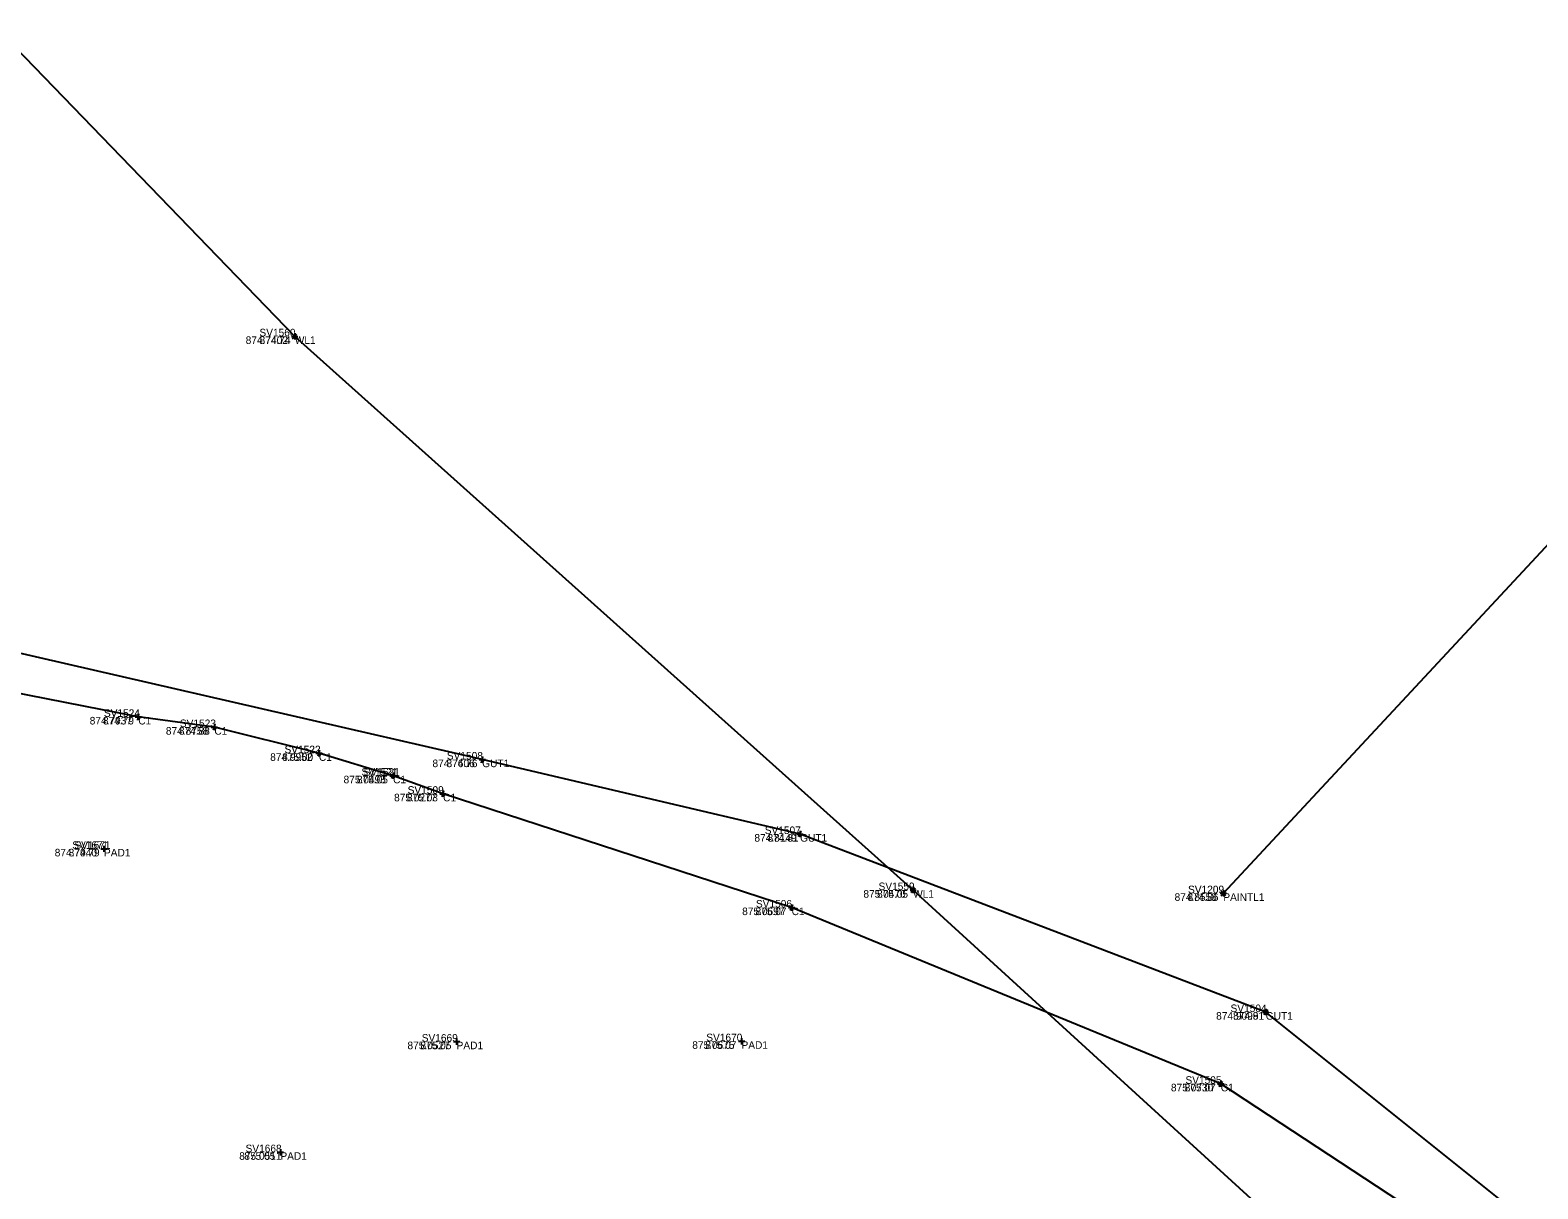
# Model space of a CAD drawing. Extents: x 1475924 to 1484301, y 375879 to 383357.
# Drawn here: x 1480175.83 to 1480187.77, y 379382.77 to 379391.95 of the extents above; entities that cross this region are included whole.
import ezdxf

# ---------------------------------------------------------------- set-up
doc = ezdxf.new("R2010")
doc.units = 0
for name, color, linetype in [('PM_X_Crosswalk', 7, 'Continuous'), ('PV_X_Curb', 7, 'Continuous'), ('SV_X_Shot_Marker', 7, 'Continuous'), ('SV_X_Text_Comment', 7, 'Continuous'), ('SV_X_Text_Elevation', 7, 'Continuous'), ('SV_X_Text_Name', 7, 'Continuous'), ('UT_X_Water', 7, 'Continuous')]:
    doc.layers.add(name, color=color, linetype=linetype)

# ---------------------------------------------------------------- blocks, each defined once
blk = doc.blocks.new('GTM')
at = {"layer": 'SV_X_Shot_Marker'}
for p, q in [((-0.075, 0), (0.075, 0)), ((0, 0.075), (0, -0.075)), ((0, 0), (0, 0))]:
    blk.add_line(p, q, dxfattribs=at)

msp = doc.modelspace()

# ---------------------------------------------------------------- linework, layer by layer
at = {"layer": 'PM_X_Crosswalk'}
msp.add_line((1480185.279, 379385.114), (1480212.329, 379414.193), dxfattribs=at)
at = {"layer": 'PV_X_Curb'}
for points in [[(1480233.83, 379339.39), (1480215.875, 379356.288), (1480200.731, 379370.664), (1480190.903, 379379.712), (1480187.53, 379382.642), (1480185.615, 379384.173), (1480181.928, 379385.583), (1480179.411, 379386.173), (1480174.793, 379387.235), (1480172.715, 379387.432), (1480170.332, 379387.359), (1480168.876, 379387.382), (1480166.808, 379386.944), (1480164.881, 379386.368), (1480162.883, 379385.531), (1480159.898, 379383.853), (1480158.052, 379382.754), (1480156.183, 379381.403), (1480155.05, 379380.342)], [(1480233.297, 379339.4), (1480215.447, 379356.074), (1480200.436, 379370.31), (1480191.889, 379378.223), (1480190.185, 379379.842), (1480188.303, 379381.604), (1480185.259, 379383.605), (1480181.861, 379385.001), (1480179.101, 379385.902), (1480178.705, 379386.045), (1480178.118, 379386.223), (1480177.29, 379386.43), (1480176.688, 379386.511), (1480174.95, 379386.851), (1480173.419, 379387.005), (1480171.202, 379387.128), (1480169.933, 379386.966), (1480168.123, 379386.781), (1480166.87, 379386.446), (1480165.488, 379386.008), (1480163.201, 379385.04), (1480160.165, 379383.332), (1480157.23, 379381.331), (1480156.058, 379380.439)]]:
    msp.add_lwpolyline(points, dxfattribs=at)
at = {"layer": 'SV_X_Shot_Marker'}
for p, q in [((1480177.946, 379389.508), (1480177.908, 379389.541)), ((1480177.91, 379389.506), (1480177.944, 379389.543)), ((1480177.927, 379389.525), (1480177.927, 379389.525)), ((1480176.713, 379386.507), (1480176.663, 379386.514)), ((1480176.685, 379386.486), (1480176.691, 379386.535)), ((1480176.688, 379386.511), (1480176.688, 379386.511)), ((1480177.314, 379386.424), (1480177.266, 379386.436)), ((1480177.284, 379386.405), (1480177.296, 379386.454)), ((1480177.29, 379386.43), (1480177.29, 379386.43)), ((1480178.142, 379386.215), (1480178.094, 379386.23)), ((1480178.111, 379386.199), (1480178.126, 379386.247)), ((1480178.118, 379386.223), (1480178.118, 379386.223)), ((1480179.435, 379386.167), (1480179.387, 379386.179)), ((1480179.405, 379386.148), (1480179.417, 379386.197)), ((1480179.411, 379386.173), (1480179.411, 379386.173)), ((1480178.728, 379386.037), (1480178.681, 379386.054)), ((1480178.696, 379386.022), (1480178.713, 379386.069)), ((1480178.705, 379386.045), (1480178.705, 379386.045)), ((1480179.124, 379385.895), (1480179.077, 379385.91)), ((1480179.093, 379385.879), (1480179.108, 379385.926)), ((1480179.101, 379385.902), (1480179.101, 379385.902)), ((1480181.951, 379385.574), (1480181.905, 379385.592)), ((1480181.919, 379385.56), (1480181.937, 379385.607)), ((1480181.928, 379385.583), (1480181.928, 379385.583)), ((1480176.391, 379385.466), (1480176.441, 379385.466)), ((1480176.416, 379385.491), (1480176.416, 379385.441)), ((1480176.416, 379385.466), (1480176.416, 379385.466)), ((1480182.842, 379385.122), (1480182.805, 379385.156)), ((1480182.806, 379385.12), (1480182.84, 379385.157)), ((1480182.823, 379385.139), (1480182.823, 379385.139)), ((1480185.26, 379385.131), (1480185.297, 379385.097)), ((1480185.261, 379385.095), (1480185.296, 379385.132)), ((1480185.279, 379385.114), (1480185.279, 379385.114)), ((1480181.884, 379384.992), (1480181.838, 379385.011)), ((1480181.851, 379384.978), (1480181.871, 379385.024)), ((1480181.861, 379385.001), (1480181.861, 379385.001)), ((1480185.635, 379384.157), (1480185.595, 379384.189)), ((1480185.599, 379384.154), (1480185.631, 379384.193)), ((1480185.615, 379384.173), (1480185.615, 379384.173)), ((1480179.183, 379383.939), (1480179.233, 379383.939)), ((1480179.208, 379383.964), (1480179.208, 379383.914)), ((1480179.208, 379383.939), (1480179.208, 379383.939)), ((1480181.439, 379383.942), (1480181.489, 379383.942)), ((1480181.464, 379383.967), (1480181.464, 379383.917)), ((1480181.464, 379383.942), (1480181.464, 379383.942)), ((1480185.28, 379383.591), (1480185.238, 379383.618)), ((1480185.245, 379383.584), (1480185.273, 379383.626)), ((1480185.259, 379383.605), (1480185.259, 379383.605)), ((1480177.788, 379383.063), (1480177.838, 379383.063)), ((1480177.813, 379383.088), (1480177.813, 379383.038)), ((1480177.813, 379383.063), (1480177.813, 379383.063))]:
    msp.add_line(p, q, dxfattribs=at)
at = {"layer": 'UT_X_Water'}
msp.add_lwpolyline([(1480234.677, 379335.863), (1480225.088, 379345.601), (1480208.322, 379361.342), (1480207.346, 379362.25), (1480199.528, 379369.768), (1480193.21, 379375.651), (1480182.823, 379385.139), (1480177.927, 379389.525), (1480169.423, 379398.321), (1480161.035, 379406.189), (1480144.924, 379421.019), (1480134.739, 379430.559), (1480121.485, 379441.998), (1480113.085, 379450.369), (1480106.418, 379456.915), (1480094.539, 379467.985), (1480089.15, 379472.551), (1480086.751, 379474.713), (1480073.459, 379487.337), (1480068.123, 379493.187), (1480050.678, 379510.207), (1480044.404, 379515.873)], dxfattribs=at)

# ---------------------------------------------------------------- block references
at = {"layer": 'SV_X_Shot_Marker', "xscale": 0.3333333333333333, "yscale": 0.3333333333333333}
for p in [(1480177.927, 379389.525), (1480176.688, 379386.511), (1480177.29, 379386.43), (1480178.118, 379386.223), (1480179.411, 379386.173), (1480178.705, 379386.045), (1480179.101, 379385.902), (1480181.928, 379385.583), (1480176.416, 379385.466), (1480182.823, 379385.139), (1480185.279, 379385.114), (1480181.861, 379385.001), (1480185.615, 379384.173), (1480179.208, 379383.939), (1480181.464, 379383.942), (1480185.259, 379383.605), (1480177.813, 379383.063)]:
    msp.add_blockref('GTM', p, dxfattribs=at)

# ---------------------------------------------------------------- texts
at = {"layer": 'SV_X_Text_Comment'}
for s, p in [('WL1', (1480177.927, 379389.465)), ('C1', (1480176.688, 379386.451)), ('C1', (1480177.29, 379386.37)), ('C1', (1480178.118, 379386.163)), ('GUT1', (1480179.411, 379386.113)), ('C1', (1480178.705, 379385.985)), ('C1', (1480179.101, 379385.842)), ('GUT1', (1480181.928, 379385.523)), ('PAD1', (1480176.416, 379385.406)), ('WL1', (1480182.823, 379385.079)), ('PAINTL1', (1480185.279, 379385.054)), ('C1', (1480181.861, 379384.941)), ('GUT1', (1480185.615, 379384.113)), ('PAD1', (1480179.208, 379383.879)), ('PAD1', (1480181.464, 379383.882)), ('C1', (1480185.259, 379383.545)), ('PAD1', (1480177.813, 379383.003))]:
    msp.add_text(s, height=0.06, dxfattribs=at).set_placement(p)
at = {"layer": 'SV_X_Text_Elevation'}
for s, p in [('874.7402', (1480177.538, 379389.465)), ('874.74', (1480177.648, 379389.465)), ('874.74', (1480177.648, 379389.465)), ('874.7937', (1480176.303, 379386.451)), ('874.79', (1480176.408, 379386.451)), ('874.79', (1480176.408, 379386.451)), ('874.8758', (1480176.906, 379386.37)), ('874.88', (1480177.009, 379386.37)), ('874.88', (1480177.009, 379386.37)), ('874.9952', (1480177.732, 379386.163)), ('875.00', (1480177.827, 379386.163)), ('875.00', (1480177.827, 379386.163)), ('874.7606', (1480179.017, 379386.113)), ('874.76', (1480179.128, 379386.113)), ('874.76', (1480179.128, 379386.113)), ('875.0498', (1480178.313, 379385.985)), ('875.05', (1480178.419, 379385.985)), ('875.05', (1480178.419, 379385.985)), ('875.0277', (1480178.713, 379385.842)), ('875.03', (1480178.815, 379385.842)), ('875.03', (1480178.815, 379385.842)), ('874.8149', (1480181.566, 379385.523)), ('874.81', (1480181.67, 379385.523)), ('874.81', (1480181.67, 379385.523)), ('874.7940', (1480176.026, 379385.406)), ('874.79', (1480176.136, 379385.406)), ('874.79', (1480176.136, 379385.406)), ('875.0470', (1480182.429, 379385.079)), ('875.05', (1480182.537, 379385.079)), ('875.05', (1480182.537, 379385.079)), ('874.8558', (1480184.893, 379385.054)), ('874.86', (1480184.995, 379385.054)), ('874.86', (1480184.995, 379385.054)), ('875.0697', (1480181.469, 379384.941)), ('875.07', (1480181.575, 379384.941)), ('875.07', (1480181.575, 379384.941)), ('874.9098', (1480185.222, 379384.113)), ('874.91', (1480185.356, 379384.113)), ('874.91', (1480185.356, 379384.113)), ('875.0527', (1480178.819, 379383.879)), ('875.05', (1480178.922, 379383.879)), ('875.05', (1480178.922, 379383.879)), ('875.0675', (1480181.074, 379383.882)), ('875.07', (1480181.178, 379383.882)), ('875.07', (1480181.178, 379383.882)), ('875.0730', (1480184.864, 379383.545)), ('875.07', (1480184.973, 379383.545)), ('875.07', (1480184.973, 379383.545)), ('875.0511', (1480177.487, 379383.003)), ('875.05', (1480177.527, 379383.003)), ('875.05', (1480177.527, 379383.003))]:
    msp.add_text(s, height=0.06, dxfattribs=at).set_placement(p)
at = {"layer": 'SV_X_Text_Name'}
for s, p in [('SV1560', (1480177.647, 379389.525)), ('SV1560', (1480177.647, 379389.525)), ('SV1560', (1480177.647, 379389.525)), ('SV1524', (1480176.416, 379386.511)), ('SV1524', (1480176.415, 379386.511)), ('SV1524', (1480176.415, 379386.511)), ('SV1523', (1480177.017, 379386.43)), ('SV1523', (1480177.017, 379386.43)), ('SV1523', (1480177.017, 379386.43)), ('SV1522', (1480177.846, 379386.223)), ('SV1522', (1480177.845, 379386.223)), ('SV1522', (1480177.845, 379386.223)), ('SV1508', (1480179.131, 379386.173)), ('SV1508', (1480179.131, 379386.173)), ('SV1508', (1480179.131, 379386.173)), ('SV1521', (1480178.455, 379386.045)), ('SV1521', (1480178.455, 379386.045)), ('SV1521', (1480178.472, 379386.045)), ('SV1509', (1480178.82, 379385.902)), ('SV1509', (1480178.821, 379385.902)), ('SV1509', (1480178.821, 379385.902)), ('SV1507', (1480181.648, 379385.583)), ('SV1507', (1480181.648, 379385.583)), ('SV1507', (1480181.648, 379385.583)), ('SV1671', (1480176.165, 379385.466)), ('SV1671', (1480176.165, 379385.466)), ('SV1671', (1480176.182, 379385.466)), ('SV1559', (1480182.549, 379385.139)), ('SV1559', (1480182.549, 379385.139)), ('SV1559', (1480182.549, 379385.139)), ('SV1209', (1480184.999, 379385.114)), ('SV1209', (1480185, 379385.114)), ('SV1209', (1480185, 379385.114)), ('SV1506', (1480181.578, 379385.001)), ('SV1506', (1480181.578, 379385.001)), ('SV1506', (1480181.578, 379385.001)), ('SV1504', (1480185.336, 379384.173)), ('SV1504', (1480185.336, 379384.173)), ('SV1504', (1480185.336, 379384.173)), ('SV1669', (1480178.932, 379383.939)), ('SV1669', (1480178.932, 379383.939)), ('SV1669', (1480178.932, 379383.939)), ('SV1670', (1480181.185, 379383.942)), ('SV1670', (1480181.185, 379383.942)), ('SV1670', (1480181.185, 379383.942)), ('SV1505', (1480184.979, 379383.605)), ('SV1505', (1480184.979, 379383.605)), ('SV1505', (1480184.979, 379383.605)), ('SV1668', (1480177.537, 379383.063)), ('SV1668', (1480177.537, 379383.063)), ('SV1668', (1480177.537, 379383.063))]:
    msp.add_text(s, height=0.06, dxfattribs=at).set_placement(p)

doc.saveas('drawing.dxf')
